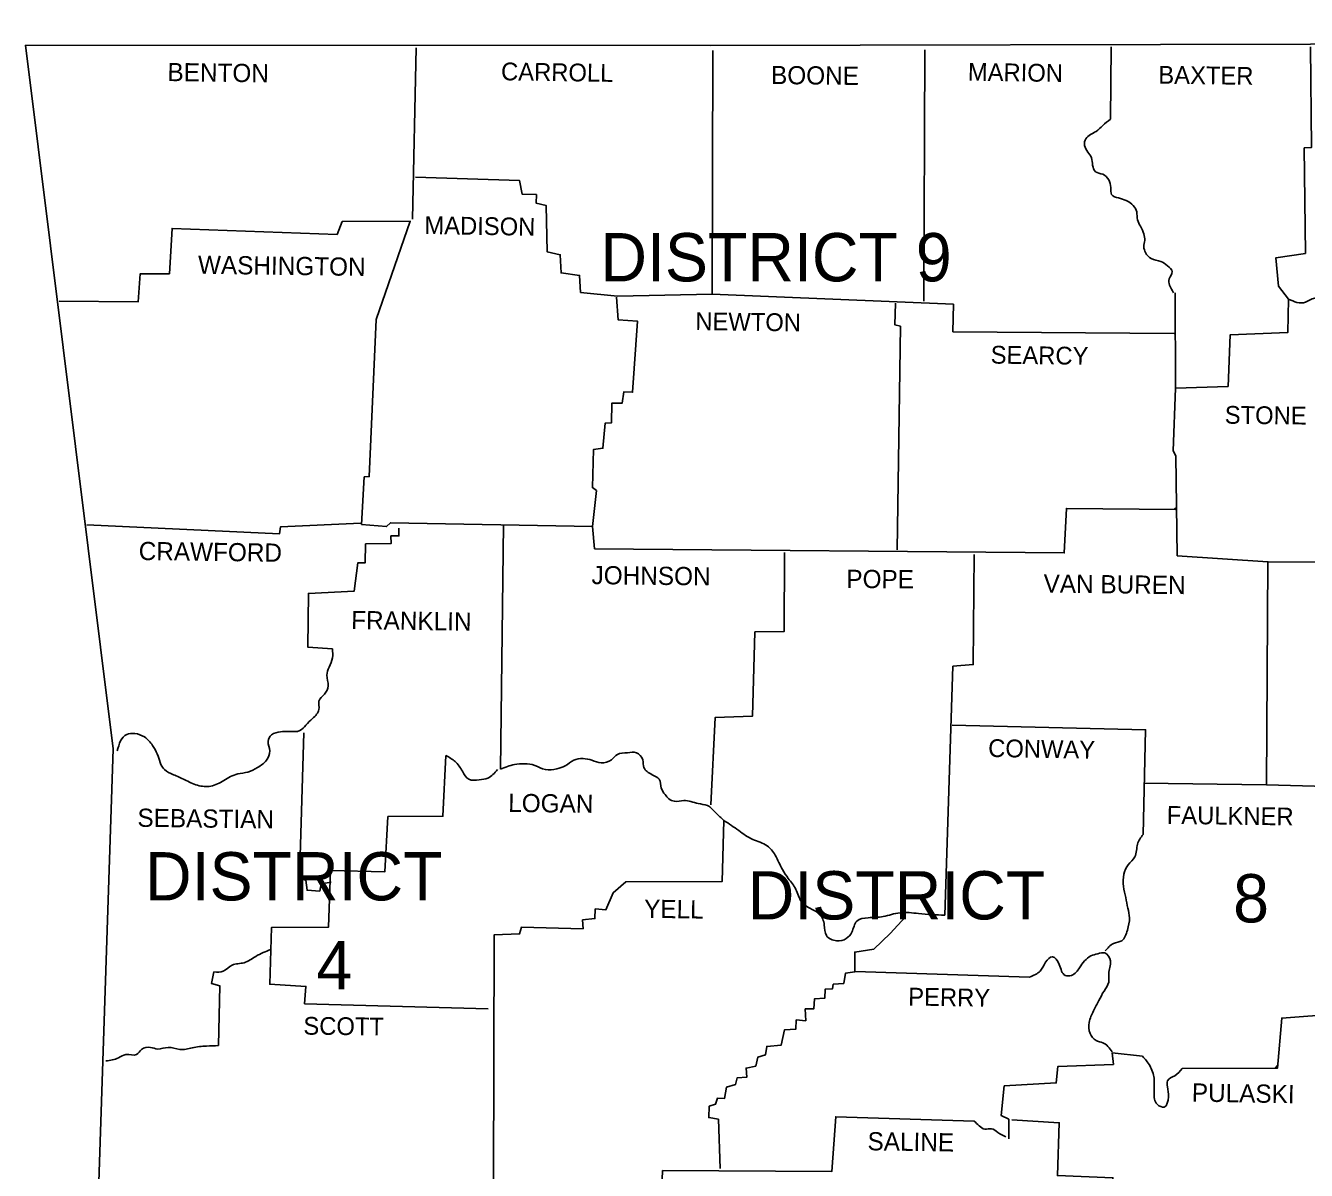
# Model space of a CAD drawing. Extents: x -42408 to 34530, y -43140 to 20491.
# Drawn here: x 1640 to 3155, y -34364 to -33011 of the extents above; entities that cross this region are included whole.
import ezdxf

# ---------------------------------------------------------------- set-up
doc = ezdxf.new("R2010")
doc.units = 0
for name, color, linetype in [('1', 7, 'Continuous'), ('2', 7, 'Continuous'), ('3', 7, 'Continuous')]:
    doc.layers.add(name, color=color, linetype=linetype)

msp = doc.modelspace()

# ---------------------------------------------------------------- linework, layer by layer
at = {"layer": '1'}
for points in [[(1640, -33034), (2449.6, -33034.5), (3160, -33033), (3998.2, -33019.9), (4386.7, -33010.9)], [(1640, -33034), (1743.7, -33866.1), (1698.6, -35224.4)], [(2102.1, -33037), (2097.6, -33239.7)], [(2101.1, -33190.2), (2224.3, -33194.2), (2227.3, -33210.2), (2244.3, -33210.7), (2243.8, -33220.7), (2255.8, -33223.7), (2256.8, -33278.3), (2272.4, -33281.8), (2273.4, -33303.3), (2295.4, -33306.3), (2296.4, -33326.3), (2340, -33330.9), (2452.1, -33328.3), (2453.1, -33040.5)], [(2703.9, -33039.5), (2702.4, -33336.9)], [(2924.2, -33036), (2923.2, -33121.6)], [(3160, -33036), (3161, -33155.1), (3152.5, -33155.6), (3154, -33280.3), (3119, -33285.3), (3122, -33318.8), (3134, -33334.4), (3133, -33373.9), (3064.9, -33376.4), (3062.4, -33437.5), (3000.3, -33439.5), (2997.3, -33513.6), (3000.8, -33519.6), (3002.3, -33637.8), (3109.5, -33644.8), (3108, -33908.6), (3193.1, -33911.1), (3193.1, -34179.5), (3126, -34184.5), (3121, -34243.6), (3008.3, -34244.1)], [(1679.6, -33336.9), (1773.2, -33337.4), (1775.7, -33304.3), (1810.2, -33304.3), (1813.3, -33250.7), (2008.5, -33257.8), (2014.5, -33242.7), (2095.1, -33242.2), (2054.6, -33358.4), (2046.6, -33544.1), (2040.6, -33544.6), (2037.5, -33600.7), (2067.1, -33603.2), (2071.6, -33598.7), (2310.4, -33603.2), (2312.9, -33629.7)], [(2452.1, -33328.3), (2737.5, -33340.4), (2737, -33372.9), (2998.8, -33374.9)], [(3000.3, -33439.5), (2999.8, -33326.8)], [(2339, -33331.9), (2341, -33358.9), (2364, -33360.4), (2358, -33444.5), (2347.5, -33444), (2345.5, -33457.5), (2333.4, -33457.5), (2332.9, -33480.6), (2325.4, -33481.1), (2322.9, -33510.6), (2311.9, -33512.1), (2310.4, -33557.2), (2315.4, -33560.7), (2310.4, -33603.2)], [(2668.9, -33338.9), (2668.4, -33364.9), (2674.9, -33366.4), (2670.9, -33630.8)], [(2312.9, -33629.7), (2868.7, -33634.3), (2871.2, -33581.7), (3000.3, -33583.2)], [(2998.8, -33582.7), (3000.3, -33581.2)], [(1712.6, -33601.2), (1940.4, -33611.7), (1941.4, -33603.7), (2036.5, -33599.2)], [(2205.3, -33601.2), (2201.8, -33890.1)], [(2081.6, -33605.2), (2081.6, -33614.2), (2072.1, -33614.2), (2072.6, -33623.2), (2042.1, -33623.7), (2041.6, -33646.3), (2033, -33646.3), (2028.5, -33679.8), (1974.5, -33682.3), (1974, -33745.9), (2003, -33747.9)], [(2537.7, -33633.8), (2537.2, -33727.4), (2502.7, -33727.9), (2499.7, -33827.5), (2455.6, -33829), (2450.6, -33932.2)], [(2762, -33636.3), (2761, -33766.4), (2737, -33768.4), (2727.5, -34062.8)], [(3109.5, -33644.8), (3366.8, -33646.3), (3388.9, -33635.8), (3387.4, -33831.5), (3372.3, -33838), (3358.8, -33849.5), (3354.3, -33854), (3353.8, -33910.1), (3190.1, -33910.1)], [(2736, -33838), (2964.8, -33843.5), (2961.8, -33967.2)], [(1969, -33847), (1964, -34019.3), (1971.5, -34021.3), (1973, -34033.3), (1988, -34034.3), (1989.5, -34025.8), (2001.5, -34023.8)], [(2137.2, -33874.1), (2133.7, -33945.7), (2068.6, -33946.2), (2065.1, -34011.3), (2000.5, -34009.8), (1998.5, -34076.8), (1930.9, -34077.3), (1928.9, -34144.4), (1971.5, -34146.9), (1970, -34167.5), (2187.2, -34173.5)], [(2962.3, -33906.6), (3108, -33908.6)], [(2466.1, -33950.7), (2464.1, -34022.8), (2350, -34023.3), (2334.9, -34036.3), (2326.4, -34056.3), (2313.9, -34055.3), (2313.4, -34066.8), (2298.9, -34068.3), (2299.4, -34078.8), (2226.8, -34076.8), (2224.3, -34084.9), (2194.3, -34085.9), (2193.3, -34378.7)], [(2680.9, -34064.8), (2662.9, -34084.4), (2643.4, -34102.9), (2620.8, -34106.4), (2620.8, -34129.9), (2609.8, -34131.4), (2607.8, -34143.4), (2595.3, -34144.4), (2594.3, -34149.9), (2585.8, -34150.4), (2585.3, -34161), (2573.3, -34161.5), (2572.3, -34173.5), (2562.2, -34173.5), (2562.8, -34187.5), (2551.7, -34186.5), (2551.2, -34197.5), (2537.7, -34198.5), (2533.7, -34216.5), (2516.7, -34218), (2515.2, -34228), (2506.2, -34230.6), (2503.7, -34241.1), (2492.2, -34243.6), (2493.2, -34254.1), (2481.6, -34255.1), (2479.6, -34263.1), (2469.1, -34266.1), (2466.6, -34279.6), (2458.6, -34279.1), (2456.1, -34286.1), (2448.6, -34288.6), (2448.1, -34302.1), (2459.6, -34304.1), (2461.6, -34362.2)], [(1868.3, -34217), (1869.8, -34146.4), (1859.8, -34143.4), (1862.8, -34129.9)], [(2827.6, -34135.9), (2621.3, -34129.4)], [(2961.3, -34229.5), (2925.2, -34225.5), (2926.7, -34239.1), (2861.1, -34241.6), (2859.1, -34261.1), (2797.6, -34264.6), (2794.1, -34299.6), (2803.1, -34304.1), (2803.1, -34327.2)], [(3118.5, -34243.1), (3121, -34240.6)], [(2762, -34306.2), (2598.3, -34301.1), (2593.8, -34365.7), (2393.5, -34364.7), (2392.5, -34386.3)], [(2806.6, -34304.6), (2862.7, -34308.2), (2860.6, -34370.7), (2926.2, -34373.2), (2927.2, -34427.8), (2958.3, -34430.3), (2958.3, -34439.8), (2987.3, -34441.8), (2988.3, -34476.9), (3054.4, -34476.9), (3056.4, -34511.4), (3117.5, -34514.4), (3117, -34579.5)]]:
    msp.add_lwpolyline(points, dxfattribs=at)
for points in [[(2923.2, -33121.6), (2914.2, -33129.1), (2906.2, -33136.1), (2894.2, -33144.6), (2892.7, -33152.6), (2896.7, -33160.6), (2900.7, -33167.1), (2902.2, -33176.1), (2905.7, -33183.7), (2914.2, -33186.7), (2921.2, -33193.2), (2923.7, -33202.2), (2924.7, -33210.7), (2932.7, -33214.7), (2941.8, -33217.7), (2950.3, -33223.7), (2954.3, -33231.2), (2955.3, -33240.7), (2958.8, -33248.2), (2962.8, -33257.3), (2963.8, -33264.8), (2962.8, -33272.3), (2964.8, -33279.3), (2971.3, -33286.3), (2982.8, -33289.8), (2990.8, -33294.8), (2996.3, -33301.8), (2992.8, -33310.3), (2993.3, -33317.8), (2997.8, -33326.8)], [(3134, -33334.4), (3154, -33337.9), (3166.1, -33333.4), (3174.6, -33346.4), (3179.1, -33356.4), (3186.6, -33370.9), (3198.6, -33375.4), (3207.6, -33383.4), (3207.6, -33391.9), (3199.6, -33399.9), (3193.6, -33408), (3195.6, -33417.5), (3197.6, -33430.5), (3197.6, -33443), (3194.6, -33454.5), (3192.1, -33465), (3194.6, -33474), (3204.1, -33472.5), (3214.1, -33465), (3224.6, -33465), (3234.6, -33470.5), (3245.2, -33480), (3255.7, -33478), (3264.2, -33475.5), (3276.2, -33472), (3284.7, -33476.5), (3292.2, -33482.6), (3301.2, -33492.1), (3309.7, -33498.1), (3320.8, -33503.6), (3334.3, -33507.1), (3346.8, -33515.6), (3348.8, -33530.1), (3348.3, -33542.6), (3347.3, -33558.2), (3346.3, -33575.2), (3347.8, -33591.7), (3353.3, -33602.7), (3360.3, -33615.7), (3362.3, -33627.7), (3361.8, -33646.8)], [(2003, -33747.9), (2003, -33758.4), (1999, -33769.4), (1996.5, -33778.9), (1998, -33791.5), (1993.5, -33801.5), (1987, -33809.5), (1987, -33819.5), (1979.5, -33830), (1971.5, -33838), (1964.5, -33844.5), (1951.9, -33845.5), (1941.4, -33846), (1930.9, -33849.5), (1926.9, -33857.1), (1928.9, -33868.6), (1924.9, -33879.6), (1914.4, -33888.1), (1902.9, -33893.6), (1890.9, -33895.6), (1874.3, -33903.6), (1859.3, -33910.1), (1843.3, -33909.1), (1828.3, -33902.6), (1814.8, -33896.6), (1804.2, -33890.6), (1795.7, -33872.1), (1790.2, -33862.1), (1780.7, -33852), (1769.2, -33848), (1759.7, -33849), (1748.2, -33868.6)], [(2137.2, -33874.1), (2148.2, -33881.1), (2156.7, -33892.6), (2164.2, -33902.1), (2176.7, -33902.6), (2186.7, -33900.6), (2198.3, -33890.6)], [(2201.8, -33890.1), (2218.3, -33884.6), (2230.3, -33883.6), (2242.3, -33885.6), (2254.8, -33890.6), (2268.4, -33889.6), (2278.4, -33886.1), (2288.4, -33879.6), (2299.4, -33877.6), (2309.9, -33879.6), (2320.9, -33882.6), (2332.9, -33879.1), (2340, -33872.6), (2352, -33870.6), (2362.5, -33870.6), (2370, -33879.1), (2371.5, -33888.1), (2381, -33896.6), (2389.5, -33902.1), (2392, -33912.6), (2396.5, -33920.1), (2401, -33925.1), (2407.5, -33928.1), (2418.6, -33927.1), (2435.6, -33930.7), (2446.6, -33933.2), (2456.6, -33941.7), (2466.1, -33950.7)], [(2466.1, -33950.7), (2483.6, -33962.7), (2500.2, -33973.2), (2517.2, -33980.7), (2526.7, -33991.7), (2535.2, -34008.8), (2542.2, -34019.3), (2551.2, -34032.3), (2557.7, -34046.8), (2568.3, -34054.8), (2579.3, -34061.8), (2584.8, -34074.3), (2587.3, -34086.9), (2599.3, -34092.9), (2610.8, -34090.4), (2617.3, -34082.9), (2623.3, -34069.8), (2636.8, -34065.8), (2654.4, -34064.3), (2674.4, -34059.8), (2696.4, -34060.8), (2727.5, -34062.8)], [(2961.8, -33967.2), (2955.3, -33978.7), (2952.3, -33993.7), (2944.3, -34003.2), (2939.3, -34014.3), (2938.8, -34028.8), (2941.3, -34041.8), (2943.8, -34054.3), (2945.8, -34065.8), (2943.3, -34080.4), (2936.7, -34092.9), (2926.7, -34096.4), (2917.2, -34104.9)], [(1862.8, -34129.9), (1873.8, -34128.9), (1884.3, -34121.9), (1898.4, -34118.9), (1912.4, -34111.4), (1929.9, -34103.4)], [(2827.6, -34135.9), (2840.1, -34128.9), (2846.6, -34118.4), (2854.6, -34111.9), (2862.7, -34120.9), (2869.7, -34133.9), (2877.2, -34133.9), (2886.7, -34124.9), (2892.7, -34116.9), (2900.2, -34110.9), (2908.2, -34108.4), (2916.7, -34107.4), (2923.2, -34116.9), (2921.2, -34131.9), (2921.2, -34141.9), (2915.7, -34152.4), (2909.7, -34163.5), (2903.2, -34176), (2898.2, -34189.5), (2899.2, -34202.5), (2906.2, -34211), (2914.2, -34213.5), (2925.2, -34224.5)], [(1868.3, -34217), (1853.8, -34217.5), (1837.3, -34219.5), (1822.3, -34221.5), (1808.7, -34219), (1796.2, -34221), (1787.7, -34219), (1777.2, -34221.5), (1771.2, -34227.5), (1758.7, -34227.5), (1749.7, -34231.6), (1735.1, -34235.1)], [(2961.3, -34229.5), (2969.8, -34240.6), (2974.8, -34255.6), (2974.8, -34272.6), (2978.8, -34286.6), (2986.8, -34289.6), (2991.8, -34277.6), (2990.8, -34265.6), (2990.8, -34258.6), (2999.3, -34252.6), (3008.3, -34244.1)], [(2799.6, -34324.7), (2790.1, -34319.7), (2782.5, -34315.2), (2774.5, -34315.7), (2768, -34311.7), (2762, -34306.2)]]:
    msp.add_spline(points, degree=3, dxfattribs=at)

# ---------------------------------------------------------------- texts
at = {"layer": '2'}
for s, height, rotation, p in [('BENTON', 21.53, 359.2527, (1807.7, -33076.5)), ('CARROLL', 21.03, 359.1481, (2202.3, -33075.5)), ('MARION', 21.03, 359.1854, (2754.5, -33076)), ('BOONE', 21.53, 359.4001, (2521.7, -33080)), ('BAXTER', 21.03, 359.2559, (2979.8, -33079.5)), ('MADISON', 21.03, 359.0906, (2111.6, -33257.3)), ('WASHINGTON', 21.52, 359.232, (1843.8, -33304.3)), ('NEWTON', 21.03, 359.2717, (2432.1, -33370.9)), ('SEARCY', 21.02, 359.2527, (2781.5, -33410.5)), ('STONE', 21.02, 359.4001, (3058.4, -33481.6)), ('CRAWFORD', 21.52, 359.2771, (1773.7, -33642.8)), ('JOHNSON', 21.53, 359.3514, (2309.4, -33671.3)), ('POPE', 21.53, 359.6155, (2610.8, -33675.8)), ('VAN BUREN', 21.53, 359.3508, (2844.1, -33681.3)), ('FRANKLIN', 21.53, 359.1815, (2025, -33724.4)), ('CONWAY', 21.02, 359.0371, (2778.5, -33875.6)), ('LOGAN', 21.53, 359.3969, (2210.8, -33940.7)), ('SEBASTIAN', 21.52, 359.2816, (1772.2, -33958.2)), ('FAULKNER', 21.03, 359.2486, (2989.8, -33954.7)), ('YELL', 21.53, 359.1987, (2371.5, -34065.8)), ('PERRY', 21.03, 359.0858, (2683.9, -34169.5)), ('SCOTT', 21.03, 359.4063, (1968.5, -34204)), ('PULASKI', 21.53, 359.053, (3019.4, -34283.1)), ('SALINE', 21.53, 359.1491, (2635.8, -34340.7))]:
    msp.add_text(s, height=height, rotation=rotation, dxfattribs=at).set_placement(p)
at = {"layer": '3'}
for s, height, p in [('DISTRICT 9', 57.08, (2319.9, -33313.3)), ('DISTRICT', 57.08, (1781.2, -34045.3)), ('DISTRICT', 57.08, (2494.2, -34067.8)), ('8', 57.1, (3068.4, -34071.3)), ('4', 57.1, (1984, -34150.4))]:
    msp.add_text(s, height=height, dxfattribs=at).set_placement(p)

doc.saveas('drawing.dxf')
